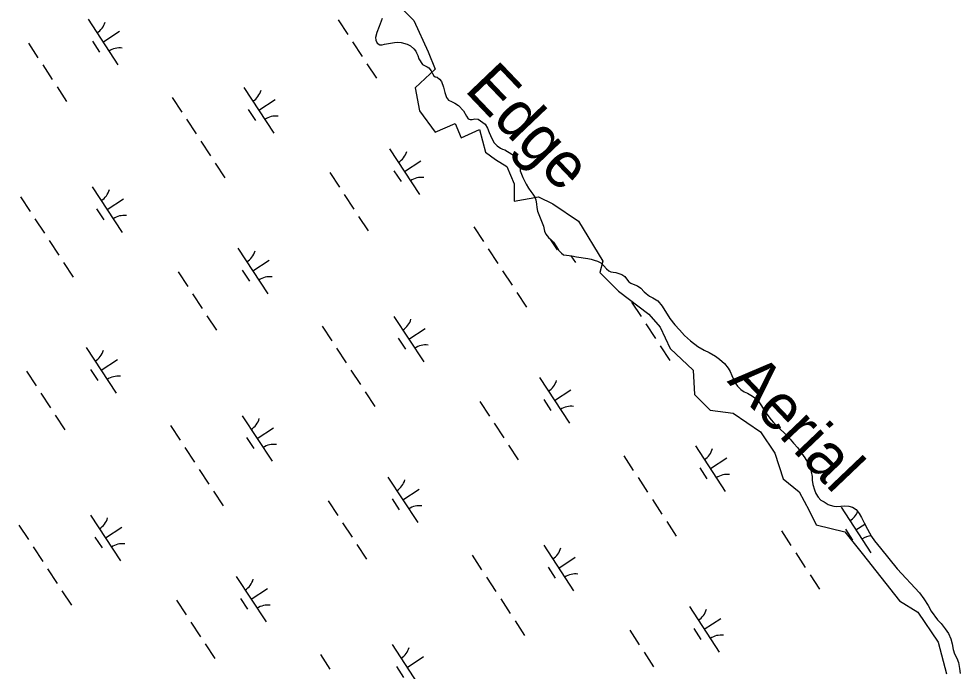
# Model space of a CAD drawing. Extents: x 3945642 to 3966284, y 206476 to 228921.
# Drawn here: x 3953536 to 3954400, y 218966 to 219564 of the extents above; entities that cross this region are included whole.
import ezdxf

# ---------------------------------------------------------------- set-up
doc = ezdxf.new("R2010")
doc.units = 0
for name, color, linetype in [('V-RIVR-EDGE', 7, 'Continuous'), ('V-RIVR-IDEN', 7, 'Continuous'), ('V-WETL-SWMP', 7, 'Continuous')]:
    doc.layers.add(name, color=color, linetype=linetype)

msp = doc.modelspace()

# ---------------------------------------------------------------- linework, layer by layer
at = {"layer": 'V-RIVR-EDGE'}
msp.add_lwpolyline([(3953881.24, 219579.72), (3953898.32, 219562.63), (3953911.47, 219533.72), (3953918.04, 219517.95), (3953899.64, 219500.87), (3953903.58, 219479.84), (3953918.04, 219460.13), (3953936.43, 219468.01), (3953941.69, 219454.87), (3953958.78, 219462.76), (3953964.03, 219441.73), (3953973.23, 219435.16), (3953983.75, 219428.59), (3953990.32, 219412.82), (3953990.32, 219397.05), (3954012.66, 219400.99), (3954025.8, 219394.42), (3954049.45, 219378.65), (3954071.79, 219341.85), (3954069.17, 219331.34), (3954086.25, 219314.26), (3954113.85, 219293.23), (3954124.36, 219281.4), (3954133.56, 219261.69), (3954154.59, 219241.98), (3954155.9, 219219.64), (3954170.36, 219205.18), (3954191.38, 219202.55), (3954216.35, 219185.47), (3954229.5, 219165.75), (3954237.38, 219142.1), (3954251.84, 219130.27), (3954261.04, 219113.19), (3954267.61, 219100.05), (3954293.89, 219093.47), (3954309.66, 219073.76), (3954343.83, 219030.39), (3954360.91, 219019.88), (3954379.31, 218992.28), (3954387.2, 218963.37)], dxfattribs=at)
at = {"layer": 'V-WETL-SWMP'}
for p, q in [((3953599.49, 219563.73), (3953626.89, 219521.9)), ((3953829.06, 219563.14), (3953837.83, 219549.75)), ((3953869.43, 219564.55), (3953866.71, 219557)), ((3953613.19, 219542.81), (3953628.24, 219552.68)), ((3953864.44, 219551.68), (3953863.25, 219547.15)), ((3953866.71, 219557), (3953864.44, 219551.68)), ((3953544.79, 219541.89), (3953553.56, 219528.5)), ((3953603.45, 219543.6), (3953610.02, 219533.57)), ((3953842.21, 219543.06), (3953850.98, 219529.68)), ((3953863.25, 219547.15), (3953863.52, 219544.56)), ((3953863.52, 219544.56), (3953864.73, 219541.67)), ((3953864.73, 219541.67), (3953867.1, 219540.35)), ((3953871.64, 219541.04), (3953880.66, 219542.56)), ((3953880.66, 219542.56), (3953883.62, 219542.61)), ((3953883.62, 219542.61), (3953886.64, 219542.3)), ((3953886.64, 219542.3), (3953892.4, 219540.82)), ((3953867.1, 219540.35), (3953869.33, 219540.41)), ((3953869.33, 219540.41), (3953871.64, 219541.04)), ((3953892.4, 219540.82), (3953895.34, 219539.36)), ((3953895.34, 219539.36), (3953898.35, 219536.53)), ((3953898.35, 219536.53), (3953900.13, 219534.49)), ((3953900.13, 219534.49), (3953900.99, 219532.98)), ((3953900.99, 219532.98), (3953901.98, 219530.52)), ((3953901.98, 219530.52), (3953903.11, 219527.48)), ((3953903.11, 219527.48), (3953906.46, 219522.27)), ((3953557.95, 219521.81), (3953566.71, 219508.43)), ((3953855.36, 219522.98), (3953864.13, 219509.6)), ((3953906.46, 219522.27), (3953908.04, 219521.25)), ((3953908.04, 219521.25), (3953910.62, 219520.22)), ((3953910.62, 219520.22), (3953912.27, 219519.2)), ((3953912.27, 219519.2), (3953914.27, 219516.52)), ((3953914.27, 219516.52), (3953915.41, 219514.14)), ((3953915.41, 219514.14), (3953916.69, 219511.82)), ((3953916.69, 219511.82), (3953918.05, 219510.95)), ((3953918.05, 219510.95), (3953919.78, 219510.5)), ((3953919.78, 219510.5), (3953922, 219508.83)), ((3953922, 219508.83), (3953923.79, 219506.58)), ((3953923.79, 219506.58), (3953925.77, 219501.38)), ((3953571.1, 219501.74), (3953579.87, 219488.35)), ((3953742.56, 219501.18), (3953769.96, 219459.36)), ((3953925.77, 219501.38), (3953926.81, 219496.62)), ((3953676.77, 219492.06), (3953685.53, 219478.68)), ((3953756.26, 219480.27), (3953771.32, 219490.14)), ((3953926.81, 219496.62), (3953928.51, 219491.92)), ((3953928.51, 219491.92), (3953930.29, 219489.6)), ((3953930.29, 219489.6), (3953932.88, 219488.36)), ((3953746.52, 219481.06), (3953753.09, 219471.02)), ((3953932.88, 219488.36), (3953936.04, 219486.68)), ((3953936.04, 219486.68), (3953939.27, 219484.71)), ((3953939.27, 219484.71), (3953943.92, 219479.63)), ((3953943.92, 219479.63), (3953946.62, 219474.86)), ((3953946.62, 219474.86), (3953948.4, 219472.47)), ((3953948.4, 219472.47), (3953950.2, 219471.88)), ((3953951.86, 219471.94), (3953954.31, 219472.43)), ((3953954.31, 219472.43), (3953957.27, 219472.12)), ((3953957.27, 219472.12), (3953963.86, 219467.46)), ((3953689.92, 219471.98), (3953698.69, 219458.6)), ((3953950.2, 219471.88), (3953951.86, 219471.94)), ((3953963.86, 219467.46), (3953965.85, 219463.91)), ((3953965.85, 219463.91), (3953967.56, 219459.94)), ((3953967.56, 219459.94), (3953969.82, 219454.44)), ((3953703.07, 219451.91), (3953711.84, 219438.52)), ((3953969.82, 219454.44), (3953972.24, 219450.46)), ((3953972.24, 219450.46), (3953974.82, 219447.78)), ((3953974.82, 219447.78), (3953977.76, 219445.6)), ((3953876.15, 219444.96), (3953903.55, 219403.13)), ((3953977.76, 219445.6), (3953979.77, 219444.72)), ((3953979.77, 219444.72), (3953982, 219443.84)), ((3953982, 219443.84), (3953988.38, 219440.05)), ((3953988.38, 219440.05), (3953991.96, 219436.49)), ((3953716.22, 219431.83), (3953724.99, 219418.45)), ((3953889.85, 219424.05), (3953904.9, 219433.91)), ((3953991.96, 219436.49), (3953994.38, 219432.43)), ((3953994.38, 219432.43), (3953995.58, 219428.61)), ((3953821.45, 219423.12), (3953830.22, 219409.74)), ((3953880.1, 219424.84), (3953886.68, 219414.8)), ((3953995.58, 219428.61), (3953996.06, 219424.64)), ((3953996.06, 219424.64), (3953997.26, 219421.61)), ((3953997.26, 219421.61), (3953998.54, 219418.71)), ((3953998.54, 219418.71), (3953999.88, 219415.68)), ((3953999.88, 219415.68), (3954001.59, 219412.42)), ((3954001.59, 219412.42), (3954003.58, 219408.81)), ((3953603.42, 219410.03), (3953630.82, 219368.21)), ((3953834.61, 219403.04), (3953843.37, 219389.66)), ((3954003.58, 219408.81), (3954005.65, 219405.76)), ((3954005.65, 219405.76), (3954007.58, 219403.3)), ((3954007.58, 219403.3), (3954009.43, 219400.48)), ((3953537.63, 219400.91), (3953546.4, 219387.52)), ((3953617.12, 219389.12), (3953632.18, 219398.98)), ((3954009.43, 219400.48), (3954010.35, 219398.09)), ((3954010.35, 219398.09), (3954010.97, 219394.27)), ((3953607.38, 219389.91), (3953613.96, 219379.87)), ((3954010.97, 219394.27), (3954011.24, 219391.24)), ((3954011.24, 219391.24), (3954011.79, 219387.78)), ((3954011.79, 219387.78), (3954017.24, 219373.83)), ((3953550.78, 219380.83), (3953559.55, 219367.45)), ((3953847.76, 219382.97), (3953856.53, 219369.59)), ((3953953.43, 219373.29), (3953962.19, 219359.91)), ((3954017.24, 219373.83), (3954018.36, 219369.5)), ((3954018.36, 219369.5), (3954019.42, 219366.54)), ((3953563.93, 219360.76), (3953572.7, 219347.37)), ((3954019.42, 219366.54), (3954021.92, 219363.57)), ((3954021.92, 219363.57), (3954024.14, 219361.6)), ((3954023.18, 219362.29), (3954029.75, 219352.26)), ((3954024.14, 219361.6), (3954026.58, 219359.14)), ((3953737.01, 219353.81), (3953764.41, 219311.98)), ((3953966.58, 219353.22), (3953975.35, 219339.83)), ((3954026.58, 219359.14), (3954029.28, 219354.87)), ((3954029.28, 219354.87), (3954031.06, 219351.83)), ((3954031.06, 219351.83), (3954033.78, 219349.07)), ((3953750.71, 219332.89), (3953765.76, 219342.76)), ((3954033.78, 219349.07), (3954035.86, 219347.76)), ((3954035.86, 219347.76), (3954038.6, 219347.23)), ((3954038.6, 219347.23), (3954040.83, 219347.07)), ((3954040.83, 219347.07), (3954043.42, 219346.7)), ((3954042.54, 219346.82), (3954046.62, 219340.59)), ((3954043.42, 219346.7), (3954047.67, 219345.8)), ((3954047.67, 219345.8), (3954057.89, 219344.43)), ((3954057.89, 219344.43), (3954061.06, 219343.61)), ((3954061.06, 219343.61), (3954063.72, 219342.87)), ((3954063.72, 219342.87), (3954066.88, 219341.84)), ((3953577.08, 219340.68), (3953585.85, 219327.3)), ((3954066.88, 219341.84), (3954069.97, 219340.24)), ((3954069.97, 219340.24), (3954072.83, 219337.62)), ((3954072.83, 219337.62), (3954075.12, 219334.79)), ((3954075.12, 219334.79), (3954077.41, 219332.9)), ((3953682.32, 219331.97), (3953691.08, 219318.58)), ((3953740.97, 219333.69), (3953747.54, 219323.65)), ((3953979.73, 219333.14), (3953988.5, 219319.76)), ((3954077.41, 219332.9), (3954079.28, 219332.17)), ((3954079.28, 219332.17), (3954081.15, 219331.8)), ((3954081.15, 219331.8), (3954083.6, 219331.35)), ((3954083.6, 219331.35), (3954086.54, 219330.53)), ((3954086.54, 219330.53), (3954089.2, 219329.65)), ((3954089.2, 219329.65), (3954092.07, 219327.83)), ((3954092.07, 219327.83), (3954093.64, 219325.66)), ((3954093.64, 219325.66), (3954095.71, 219322.83)), ((3954095.71, 219322.83), (3954097.51, 219321.59)), ((3954097.51, 219321.59), (3954101.03, 219320.27)), ((3954101.03, 219320.27), (3954103.54, 219319.24)), ((3954103.54, 219319.24), (3954106.77, 219317.06)), ((3954106.77, 219317.06), (3954109.63, 219313.87)), ((3953695.47, 219311.89), (3953704.24, 219298.51)), ((3953992.88, 219313.06), (3954001.65, 219299.68)), ((3954109.63, 219313.87), (3954111.56, 219312.27)), ((3954111.56, 219312.27), (3954114.72, 219309.8)), ((3954114.72, 219309.8), (3954117.73, 219308.33)), ((3954117.73, 219308.33), (3954122.11, 219305.42)), ((3954098.11, 219304.35), (3954106.88, 219290.97)), ((3954122.11, 219305.42), (3954126.33, 219300.71)), ((3954126.33, 219300.71), (3954133.38, 219289.34)), ((3953708.62, 219291.82), (3953717.39, 219278.43)), ((3953880.08, 219291.26), (3953907.48, 219249.44)), ((3953814.29, 219282.14), (3953823.06, 219268.76)), ((3954111.27, 219284.28), (3954120.03, 219270.89)), ((3954133.38, 219289.34), (3954137.88, 219283.62)), ((3954137.88, 219283.62), (3954142.1, 219278.83)), ((3953893.78, 219270.35), (3953908.84, 219280.22)), ((3954142.1, 219278.83), (3954146.81, 219273.75)), ((3954146.81, 219273.75), (3954152.18, 219268.74)), ((3953884.04, 219271.14), (3953890.61, 219261.11)), ((3954152.18, 219268.74), (3954159.07, 219263.72)), ((3953597.87, 219262.65), (3953625.27, 219220.83)), ((3953827.44, 219262.06), (3953836.21, 219248.68)), ((3954124.42, 219264.2), (3954133.18, 219250.82)), ((3954159.07, 219263.72), (3954164.81, 219260.37)), ((3954164.81, 219260.37), (3954169.26, 219258.1)), ((3954169.26, 219258.1), (3954175.07, 219254.6)), ((3953611.57, 219241.74), (3953626.63, 219251.61)), ((3954175.07, 219254.6), (3954178.94, 219251.98)), ((3954178.94, 219251.98), (3954183.31, 219247.91)), ((3954183.31, 219247.91), (3954186.74, 219243.71)), ((3953543.18, 219240.82), (3953551.94, 219227.43)), ((3953601.83, 219242.53), (3953608.4, 219232.5)), ((3953840.59, 219241.99), (3953849.36, 219228.61)), ((3954186.74, 219243.71), (3954188.52, 219240.74)), ((3954188.52, 219240.74), (3954190.22, 219237.05)), ((3954013.67, 219235.04), (3954041.07, 219193.21)), ((3954190.22, 219237.05), (3954191.64, 219233.59)), ((3954191.64, 219233.59), (3954192.99, 219230.69)), ((3954192.99, 219230.69), (3954195.48, 219227.15)), ((3953853.74, 219221.91), (3953862.51, 219208.53)), ((3954027.37, 219214.13), (3954042.42, 219223.99)), ((3954195.48, 219227.15), (3954198.35, 219224.17)), ((3954198.35, 219224.17), (3954201.5, 219222.06)), ((3954201.5, 219222.06), (3954204.45, 219220.67)), ((3953556.33, 219220.74), (3953565.1, 219207.36)), ((3953958.97, 219213.2), (3953967.74, 219199.82)), ((3954017.62, 219214.92), (3954024.2, 219204.88)), ((3954204.45, 219220.67), (3954207.53, 219219.06)), ((3954207.53, 219219.06), (3954210.98, 219216.95)), ((3954210.98, 219216.95), (3954214.13, 219214.33)), ((3954214.13, 219214.33), (3954218.98, 219206.8)), ((3954218.98, 219206.8), (3954220.97, 219203.4)), ((3953569.48, 219200.67), (3953578.25, 219187.28)), ((3953740.94, 219200.11), (3953768.34, 219158.29)), ((3954220.97, 219203.4), (3954223.11, 219200.21)), ((3954223.11, 219200.21), (3954226.25, 219196.3)), ((3954226.25, 219196.3), (3954228.47, 219193.98)), ((3953675.15, 219190.99), (3953683.92, 219177.61)), ((3953754.64, 219179.2), (3953769.7, 219189.06)), ((3953972.13, 219193.13), (3953980.89, 219179.74)), ((3954228.47, 219193.98), (3954231.47, 219190.86)), ((3954231.47, 219190.86), (3954234.55, 219187.81)), ((3954234.55, 219187.81), (3954238.06, 219184.54)), ((3953744.9, 219179.99), (3953751.48, 219169.95)), ((3954238.06, 219184.54), (3954243.64, 219178.74)), ((3954243.64, 219178.74), (3954246.85, 219174.97)), ((3953688.3, 219170.91), (3953697.07, 219157.53)), ((3953985.28, 219173.05), (3953994.05, 219159.67)), ((3954156.74, 219172.5), (3954184.14, 219130.67)), ((3954246.85, 219174.97), (3954250.79, 219170.54)), ((3954250.79, 219170.54), (3954254.21, 219165.69)), ((3954090.95, 219163.37), (3954099.71, 219149.99)), ((3954170.44, 219151.58), (3954185.5, 219161.45)), ((3954254.21, 219165.69), (3954257.21, 219161.49)), ((3954257.21, 219161.49), (3954259.63, 219157.65)), ((3954259.63, 219157.65), (3954261.9, 219152.88)), ((3954261.9, 219152.88), (3954263.71, 219144.22)), ((3953701.45, 219150.84), (3953710.22, 219137.45)), ((3953874.53, 219143.89), (3953901.93, 219102.06)), ((3954160.7, 219152.38), (3954167.27, 219142.34)), ((3954263.71, 219144.22), (3954263.76, 219141.12)), ((3954104.1, 219143.3), (3954112.87, 219129.91)), ((3954263.76, 219141.12), (3954264.6, 219136.87)), ((3954264.6, 219136.87), (3954265.86, 219132.03)), ((3953714.6, 219130.76), (3953723.37, 219117.38)), ((3953888.23, 219122.98), (3953903.28, 219132.84)), ((3954265.86, 219132.03), (3954267.13, 219128.71)), ((3954267.13, 219128.71), (3954269.2, 219125.45)), ((3953819.84, 219122.05), (3953828.6, 219108.67)), ((3953878.49, 219123.77), (3953885.06, 219113.73)), ((3954117.25, 219123.22), (3954126.02, 219109.84)), ((3954269.2, 219125.45), (3954271.77, 219122.76)), ((3954271.77, 219122.76), (3954274.79, 219121.16)), ((3954274.79, 219121.16), (3954278.45, 219118.82)), ((3954278.45, 219118.82), (3954280.39, 219118.16)), ((3954280.39, 219118.16), (3954283.63, 219117.2)), ((3954283.63, 219117.2), (3954286.43, 219116.89)), ((3954286.43, 219116.89), (3954290.18, 219117.08)), ((3954290.18, 219117.08), (3954293.5, 219117.35)), ((3954290.33, 219116.27), (3954317.73, 219074.45)), ((3954293.5, 219117.35), (3954297.6, 219117.17)), ((3954297.6, 219117.17), (3954300.98, 219116.21)), ((3954300.98, 219116.21), (3954304.29, 219114.1)), ((3954304.29, 219114.1), (3954307.07, 219110.48)), ((3954307.07, 219110.48), (3954308.99, 219106.79)), ((3953601.8, 219108.96), (3953629.2, 219067.14)), ((3953832.99, 219101.97), (3953841.76, 219088.59)), ((3954130.4, 219103.15), (3954139.17, 219089.76)), ((3954304.03, 219095.36), (3954312.17, 219100.69)), ((3954308.99, 219106.79), (3954311.55, 219101.94)), ((3954311.55, 219101.94), (3954314.53, 219095.94)), ((3953536.01, 219099.84), (3953544.78, 219086.45)), ((3953615.5, 219088.05), (3953630.56, 219097.91)), ((3954235.63, 219094.43), (3954244.4, 219081.05)), ((3954294.28, 219096.15), (3954300.86, 219086.11)), ((3954314.53, 219095.94), (3954318.31, 219089.36)), ((3953605.76, 219088.84), (3953612.34, 219078.8)), ((3954318.31, 219089.36), (3954321.09, 219085.45)), ((3954321.09, 219085.45), (3954326.52, 219078.49)), ((3953549.16, 219079.76), (3953557.93, 219066.38)), ((3953846.14, 219081.9), (3953854.91, 219068.51)), ((3954017.6, 219081.35), (3954045, 219039.52)), ((3954326.52, 219078.49), (3954341.95, 219059.64)), ((3953951.81, 219072.22), (3953960.58, 219058.84)), ((3954031.3, 219060.43), (3954046.36, 219070.3)), ((3954248.79, 219074.36), (3954257.55, 219060.97)), ((3953562.31, 219059.69), (3953571.08, 219046.3)), ((3954021.56, 219061.22), (3954028.14, 219051.19)), ((3954341.95, 219059.64), (3954362.18, 219037.52)), ((3953735.39, 219052.74), (3953762.79, 219010.91)), ((3953964.96, 219052.15), (3953973.73, 219038.76)), ((3954261.94, 219054.28), (3954270.71, 219040.9)), ((3953749.09, 219031.82), (3953764.15, 219041.69)), ((3953575.47, 219039.61), (3953584.23, 219026.23)), ((3953739.35, 219032.61), (3953745.92, 219022.58)), ((3953978.11, 219032.07), (3953986.88, 219018.69)), ((3954362.18, 219037.52), (3954366.4, 219032.16)), ((3954366.4, 219032.16), (3954370.24, 219026.15)), ((3953680.7, 219030.9), (3953689.47, 219017.51)), ((3954151.19, 219025.12), (3954178.59, 218983.3)), ((3954370.24, 219026.15), (3954372.87, 219020.73)), ((3954372.87, 219020.73), (3954378.87, 219012.9)), ((3953693.85, 219010.82), (3953702.62, 218997.44)), ((3953991.26, 219011.99), (3954000.03, 218998.61)), ((3954164.89, 219004.21), (3954179.94, 219014.07)), ((3954378.87, 219012.9), (3954382.16, 219009.42)), ((3954382.16, 219009.42), (3954385.87, 219004.71)), ((3954096.5, 219003.28), (3954105.26, 218989.9)), ((3954155.15, 219005), (3954161.72, 218994.96)), ((3954385.87, 219004.71), (3954388.94, 219000.29)), ((3954388.94, 219000.29), (3954391.21, 218995.59)), ((3953707, 218990.75), (3953715.77, 218977.36)), ((3953878.46, 218990.19), (3953905.86, 218948.37)), ((3954391.21, 218995.59), (3954392.4, 218990.9)), ((3954392.4, 218990.9), (3954393.23, 218985.78)), ((3953812.67, 218981.07), (3953821.44, 218967.69)), ((3954109.65, 218983.21), (3954118.41, 218969.82)), ((3954393.23, 218985.78), (3954394.43, 218981.8)), ((3954394.43, 218981.8), (3954396.49, 218977.61)), ((3953892.16, 218969.28), (3953907.22, 218979.15)), ((3954396.49, 218977.61), (3954398.19, 218973.85)), ((3954398.19, 218973.85), (3954399.09, 218968.22)), ((3953882.42, 218970.07), (3953889, 218960.04)), ((3954399.09, 218968.22), (3954399.63, 218963.54))]:
    msp.add_line(p, q, dxfattribs=at)
for centre, start, end in [((3953598.25, 219566.05), 302.45745, 344.00111), ((3953628.52, 219519.84), 82.45745, 124.00111), ((3953741.32, 219503.51), 302.45745, 344.00111), ((3953771.6, 219457.3), 82.45745, 124.00111), ((3953874.91, 219447.28), 302.45745, 344.00111), ((3953905.18, 219401.07), 82.45745, 124.00111), ((3953602.18, 219412.36), 302.45745, 344.00111), ((3953632.46, 219366.15), 82.45745, 124.00111), ((3953735.77, 219356.13), 302.45745, 344.00111), ((3953766.04, 219309.92), 82.45745, 124.00111), ((3953878.84, 219293.59), 302.45745, 344.00111), ((3953909.12, 219247.38), 82.45745, 124.00111), ((3953596.63, 219264.98), 302.45745, 344.00111), ((3953626.9, 219218.77), 82.45745, 124.00111), ((3954012.43, 219237.36), 302.45745, 344.00111), ((3954042.7, 219191.15), 82.45745, 124.00111), ((3953739.7, 219202.44), 302.45745, 344.00111), ((3953769.98, 219156.23), 82.45745, 124.00111), ((3954155.5, 219174.82), 302.45745, 344.00111), ((3954185.77, 219128.61), 82.45745, 124.00111), ((3953873.29, 219146.21), 302.45745, 344.00111), ((3953903.56, 219100), 82.45745, 124.00111), ((3954289.09, 219118.59), 302.45745, 339.4395), ((3953600.57, 219111.28), 302.45745, 344.00111), ((3954319.36, 219072.38), 94.54628, 124.00111), ((3953630.84, 219065.07), 82.45745, 124.00111), ((3954016.36, 219083.67), 302.45745, 344.00111), ((3953734.15, 219055.06), 302.45745, 344.00111), ((3954046.64, 219037.46), 82.45745, 124.00111), ((3953764.42, 219008.85), 82.45745, 124.00111), ((3954149.95, 219027.44), 302.45745, 344.00111), ((3954180.22, 218981.23), 82.45745, 124.00111), ((3953877.22, 218992.52), 302.45745, 344.00111)]:
    msp.add_arc(centre, 17.62, start, end, dxfattribs=at)

# ---------------------------------------------------------------- texts
at = {"layer": 'V-RIVR-IDEN'}
for s, rotation, p in [('Edge', 313.64545, (3953944.08, 219498.65)), ('Aerial', 313.59639, (3954185.17, 219231.4))]:
    msp.add_text(s, height=42, rotation=rotation, dxfattribs=at).set_placement(p)

doc.saveas('drawing.dxf')
